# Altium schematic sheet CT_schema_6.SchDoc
size 287 x 160 mm
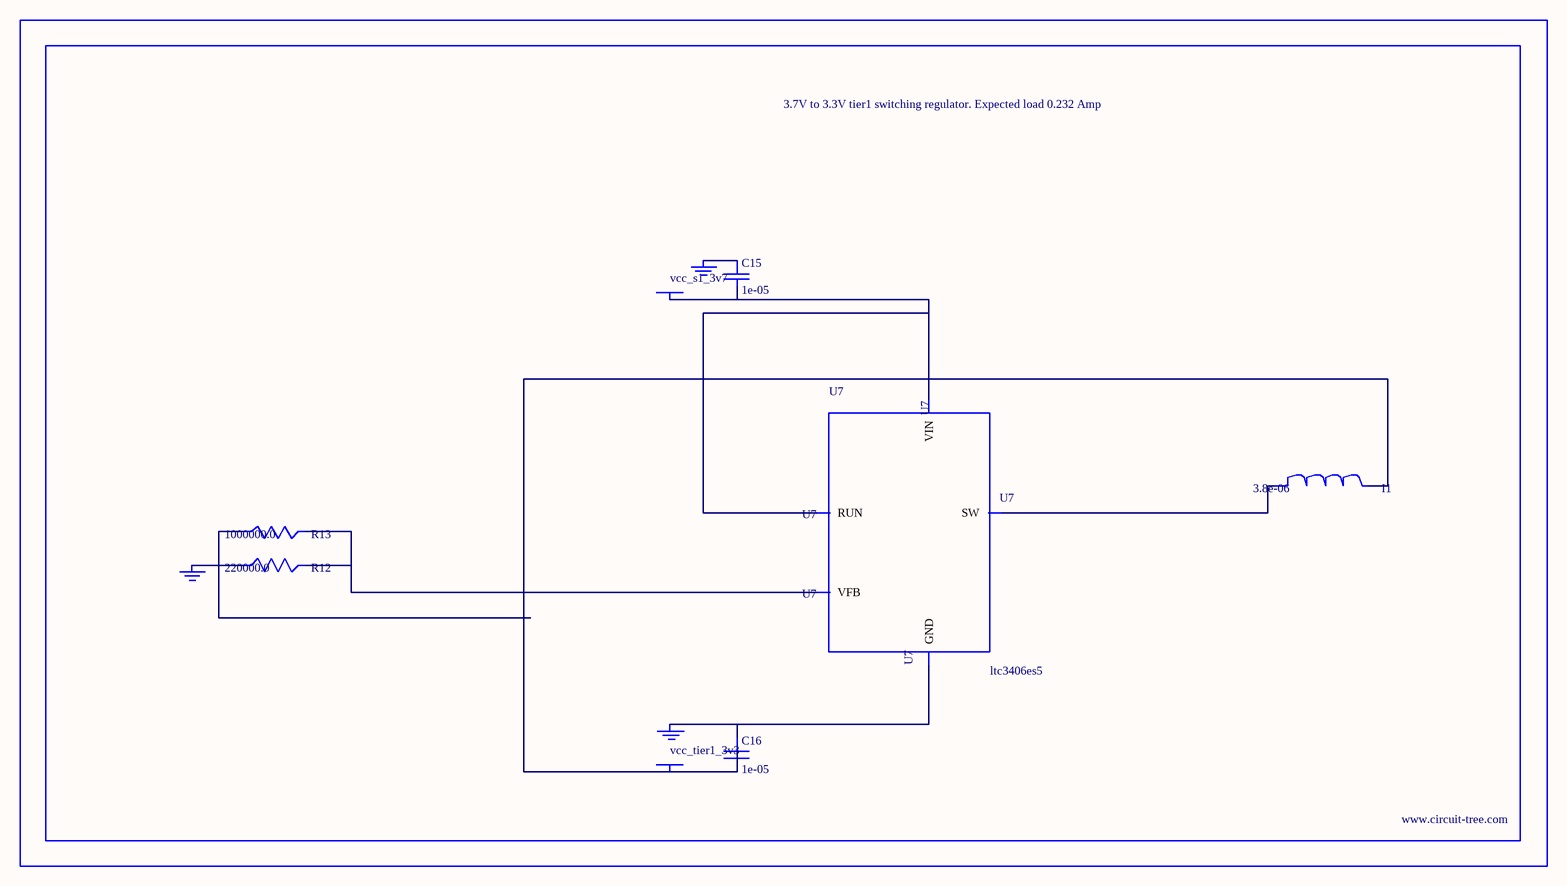
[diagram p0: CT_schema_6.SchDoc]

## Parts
BORDER5  (no value)
C15  1e-05  [C0805]
C16  1e-05  [C0805]
GND_INSTANCE_5_0  (no value)
GND_INSTANCE_5_1  (no value)
GND_INSTANCE_5_2  (no value)
I1  3.8e-06  [DR1040]
POWER_INSTANCE_5_0  vcc_tier1_3v3
POWER_INSTANCE_5_1  vcc_s1_3v7
R12  220000.0  [R0603]
R13  1000000.0  [R0603]
U7  ltc3406es5  [TSOT-23-5]

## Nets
NetC15_1: C15.1 GND_INSTANCE_5_1.0(GND)
NetC15_2: C15.2 POWER_INSTANCE_5_1.0(PWR) U7.1(RUN) U7.4(VIN)
NetC16_1: C16.1 GND_INSTANCE_5_0.0(GND) U7.2(GND)
NetC16_2: C16.2 I1.2 POWER_INSTANCE_5_0.0(PWR) R13.1
NetGND_INSTANCE_5_2_0: GND_INSTANCE_5_2.0(GND) R12.1
NetI1_1: I1.1 U7.3(SW)
NetR12_2: R12.2 R13.2 U7.5(VFB)

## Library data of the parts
BORDER5 = BORDER_PAGE5
C15 C16 = C0805C106K8RACTU
GND_INSTANCE_5_0-GND_INSTANCE_5_2 = GND
I1 = DR1040-3R8-R
POWER_INSTANCE_5_0 POWER_INSTANCE_5_1 = PWR
R12 = RC0603JR-07220KL
R13 = RC0603JR-071ML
